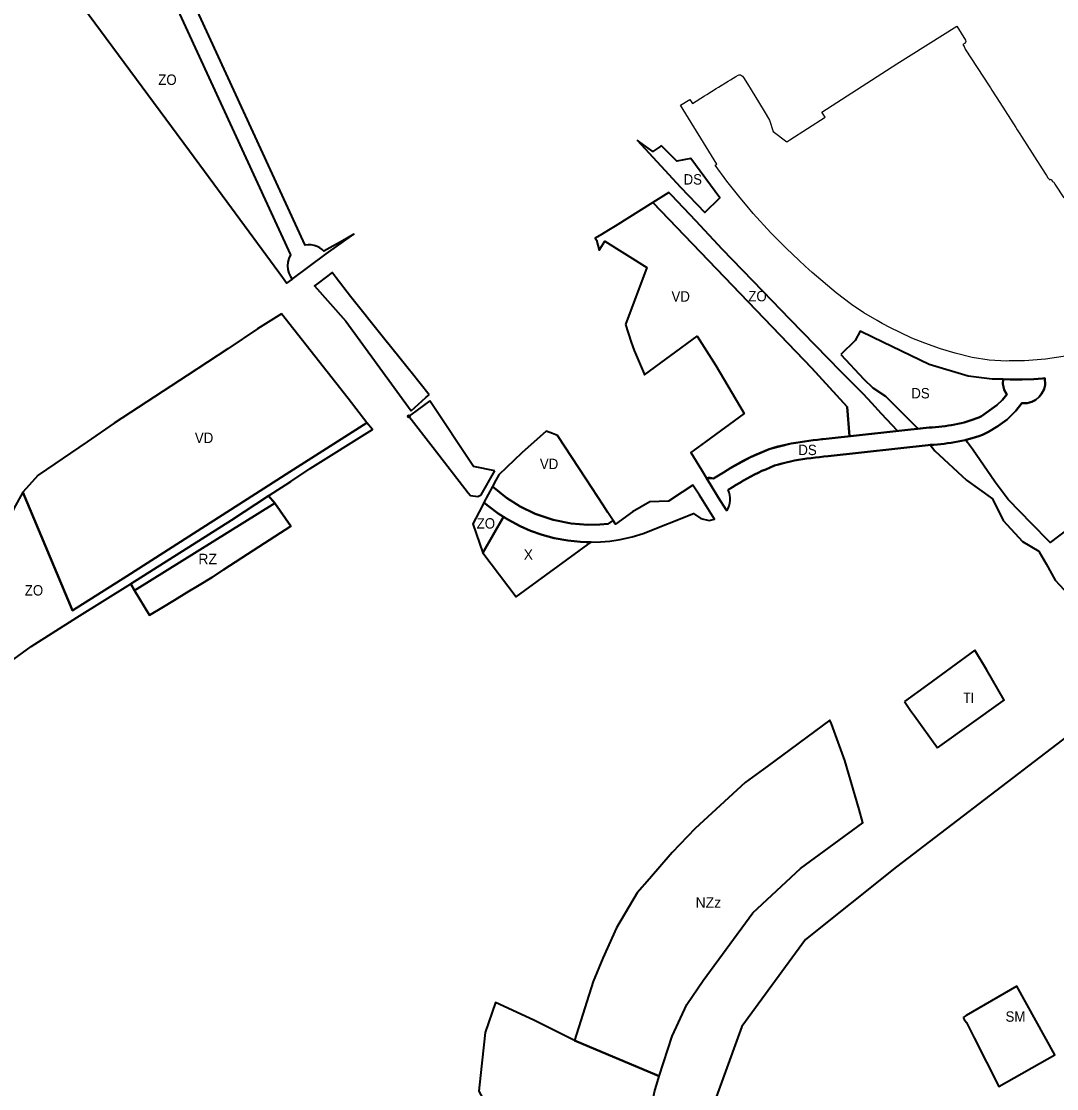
# Model space of a CAD drawing. Extents: x -650276 to -642489, y -1074311 to -1066720.
# Drawn here: x -647921 to -646730, y -1072933 to -1071705 of the extents above; entities that cross this region are included whole.
import ezdxf

# ---------------------------------------------------------------- set-up
doc = ezdxf.new("R2010")
doc.units = 0
doc.header["$LTSCALE"] = 4.8
doc.header["$PDMODE"] = 32
doc.header["$PDSIZE"] = 2.4
for name, color, linetype, lineweight in [('15', 7, 'Continuous', 35), ('18', 7, 'Continuous', 35), ('24', 7, 'Continuous', 35), ('30', 7, 'Continuous', 35), ('35', 7, 'Continuous', 35), ('42', 7, 'Continuous', 35), ('46', 7, 'Continuous', 35), ('48', 7, 'Continuous', 35), ('51', 7, 'Continuous', 35), ('54', 7, 'Continuous', 35), ('61', 7, 'Continuous', 25), ('8', 7, 'Continuous', 35)]:
    doc.layers.add(name, color=color, linetype=linetype, lineweight=lineweight)
doc.layers.add('62', color=7, linetype='Continuous')

msp = doc.modelspace()

# ---------------------------------------------------------------- linework, layer by layer
at = {"layer": '15'}
msp.add_lwpolyline([(-647795.4, -1072352.415), (-647679.66, -1072279.15), (-647637.082, -1072251.377), (-647629.67, -1072259.82), (-647791.198, -1072360.119)], close=True, dxfattribs=at)
for points in [[(-647629.67, -1072259.82), (-647637.082, -1072251.377), (-647679.66, -1072279.15)], [(-647679.66, -1072279.15), (-647795.4, -1072352.415), (-647791.198, -1072360.119), (-647629.67, -1072259.82)]]:
    msp.add_lwpolyline(points, dxfattribs=at)
at = {"layer": '18'}
msp.add_lwpolyline([(-646837.81, -1072851.3), (-646836.5, -1072853.76), (-646833.67, -1072857.15), (-646824.89, -1072874.66), (-646796.68, -1072930.92), (-646732.28, -1072894.29), (-646775.85, -1072815.39), (-646834.08, -1072849.15)], close=True, dxfattribs=at)
at = {"layer": '24'}
for p, q in [((-646978.602, -1072088.66), (-646951.95, -1072116.84)), ((-647113.646, -1072224.274), (-647124.81, -1072231.168))]:
    msp.add_line(p, q, dxfattribs=at)
for points in [[(-647782.97, -1071619.278), (-647769.498, -1071636.647), (-647758.994, -1071653.513), (-647743.48, -1071687.426), (-647611.514, -1071974.086)], [(-647570.747, -1071972.644), (-647538.922, -1071950.099), (-647551.962, -1071958.049), (-647573.283, -1071969.627), (-647575.415, -1071967.709), (-647577.881, -1071965.979), (-647581.036, -1071964.346), (-647584.363, -1071963.196), (-647588.064, -1071962.51), (-647591.518, -1071962.387), (-647594.731, -1071962.714), (-647725.614, -1071678.405), (-647726.774, -1071675.885), (-647725.629, -1071678.373)], [(-647184.81, -1071848.61), (-647185.62, -1071849.12), (-647194.96, -1071854.93), (-647205.62, -1071847.24), (-647212.66, -1071842.15)], [(-647212.66, -1071842.15), (-647163.08, -1071896.13), (-647135.015, -1071925.145), (-647135.015, -1071925.145)], [(-647135.015, -1071925.145), (-647135.015, -1071925.145), (-647117.709, -1071908.3), (-647151.07, -1071863.08), (-647167.15, -1071866.22), (-647184.81, -1071848.61)], [(-647611.514, -1071974.086), (-647613.455, -1071978.031), (-647614.654, -1071982.238), (-647615.083, -1071986.65), (-647614.76, -1071990.762), (-647613.637, -1071995.081), (-647611.779, -1071999.069), (-647609.808, -1072001.962), (-647570.747, -1071972.644)], [(-647542.57, -1072021.99), (-647558.97, -1072000.62), (-647563.77, -1071994.38), (-647579.885, -1072006.501)], [(-647579.885, -1072006.501), (-647584.202, -1072009.747), (-647547.916, -1072050.439), (-647473.022, -1072153.375)], [(-647452.23, -1072134.91), (-647472.86, -1072109.13), (-647474.72, -1072106.81), (-647485.6, -1072093.2), (-647504.73, -1072069.29), (-647542.57, -1072021.99)], [(-646790.432, -1072129.195), (-646791.977, -1072122.305), (-646791.84, -1072117.172), (-646804.27, -1072116.98), (-646832.01, -1072113.66), (-646876.83, -1072100.12), (-646941.054, -1072069.172), (-646956.04, -1072061.95), (-646962.041, -1072072.379), (-646978.602, -1072088.66)], [(-646951.95, -1072116.84), (-646941.45, -1072126.84), (-646927.14, -1072136.74), (-646891.05, -1072172.79), (-646890.044, -1072174.056), (-646876.712, -1072172.592), (-646873.495, -1072172.799), (-646862.09, -1072171.444), (-646840.102, -1072167.623), (-646825.169, -1072163.164), (-646816.74, -1072159.571), (-646799, -1072147), (-646792.58, -1072140.847), (-646787.481, -1072134.643), (-646790.432, -1072129.195)], [(-646816.74, -1072159.571), (-646799, -1072147), (-646792.58, -1072140.847), (-646787.481, -1072134.643), (-646790.343, -1072129.36), (-646791.977, -1072122.305), (-646791.84, -1072117.172), (-646783.449, -1072117.302), (-646769.668, -1072117.517), (-646756.298, -1072117), (-646746.547, -1072116.221), (-646743.596, -1072115.985), (-646743.411, -1072123.612), (-646744.554, -1072128.415), (-646747.39, -1072134.069), (-646750.164, -1072137.467), (-646753.929, -1072140.612), (-646758.736, -1072143.137), (-646763.959, -1072144.535), (-646770.057, -1072144.677), (-646777.129, -1072153.576), (-646787.223, -1072163.402), (-646797.713, -1072171.151), (-646808.466, -1072177.78)], [(-646808.466, -1072177.78), (-646797.713, -1072171.151), (-646787.223, -1072163.402), (-646777.129, -1072153.576), (-646770.057, -1072144.677), (-646763.959, -1072144.535), (-646758.736, -1072143.137), (-646753.929, -1072140.612), (-646750.164, -1072137.467), (-646747.39, -1072134.069), (-646744.554, -1072128.415), (-646743.411, -1072123.612), (-646743.596, -1072115.985), (-646746.547, -1072116.221), (-646756.298, -1072117), (-646769.668, -1072117.517), (-646783.449, -1072117.302), (-646791.84, -1072117.172), (-646791.977, -1072122.305), (-646790.343, -1072129.36), (-646787.481, -1072134.643), (-646792.58, -1072140.847), (-646799, -1072147), (-646816.74, -1072159.571)], [(-647451.21, -1072142.08), (-647473.12, -1072157.91), (-647475.57, -1072159.74), (-647475.57, -1072159.74)], [(-647473.022, -1072153.375), (-647455.83, -1072137.96), (-647452.23, -1072134.91)], [(-647376.68, -1072222.29), (-647401.221, -1072217.342), (-647451.21, -1072142.08)], [(-647475.57, -1072159.74), (-647447.73, -1072195.72), (-647407.34, -1072247.93)], [(-647124.81, -1072231.168), (-647113.646, -1072224.274), (-647109.342, -1072221.634), (-647104.989, -1072219.005), (-647100.583, -1072216.405), (-647096.114, -1072213.845), (-647091.574, -1072211.346), (-647086.955, -1072208.921), (-647082.249, -1072206.591), (-647077.456, -1072204.373), (-647072.72, -1072202.352), (-647060.973, -1072197.439), (-647055.906, -1072195.893), (-647050.82, -1072194.5), (-647045.722, -1072193.245), (-647040.618, -1072192.117), (-647035.515, -1072191.104), (-647030.417, -1072190.192), (-647025.33, -1072189.37), (-647020.254, -1072188.623), (-647015.192, -1072187.939), (-647010.148, -1072187.308), (-647005.124, -1072186.715), (-647000.12, -1072186.148), (-646995.137, -1072185.597), (-646876.712, -1072172.592), (-646873.495, -1072172.799), (-646869.667, -1072172.366), (-646865.866, -1072171.917), (-646862.09, -1072171.444), (-646858.343, -1072170.937), (-646854.627, -1072170.389), (-646850.941, -1072169.791), (-646847.291, -1072169.137), (-646843.678, -1072168.416), (-646840.102, -1072167.623), (-646836.573, -1072166.751), (-646833.091, -1072165.791), (-646829.66, -1072164.739), (-646826.287, -1072163.588), (-646822.975, -1072162.332), (-646819.733, -1072160.968), (-646816.74, -1072159.571)], [(-646816.74, -1072159.571), (-646819.733, -1072160.968), (-646822.975, -1072162.332), (-646826.287, -1072163.588), (-646829.66, -1072164.739), (-646833.091, -1072165.791), (-646836.573, -1072166.751), (-646840.102, -1072167.623), (-646843.678, -1072168.416), (-646847.291, -1072169.137), (-646850.941, -1072169.791), (-646854.627, -1072170.389), (-646858.343, -1072170.937), (-646862.09, -1072171.444), (-646865.866, -1072171.917), (-646869.667, -1072172.366), (-646873.495, -1072172.799), (-646876.712, -1072172.592), (-646995.137, -1072185.597), (-647000.12, -1072186.148), (-647005.124, -1072186.715), (-647010.148, -1072187.308), (-647015.192, -1072187.939), (-647020.254, -1072188.623), (-647025.33, -1072189.37), (-647030.417, -1072190.192), (-647035.515, -1072191.104), (-647040.618, -1072192.117), (-647045.722, -1072193.245), (-647050.82, -1072194.5), (-647055.906, -1072195.893), (-647060.973, -1072197.439), (-647072.72, -1072202.352), (-647077.456, -1072204.373), (-647082.249, -1072206.591), (-647086.955, -1072208.921), (-647091.574, -1072211.346), (-647096.114, -1072213.845), (-647100.583, -1072216.405), (-647104.989, -1072219.005), (-647109.342, -1072221.634), (-647113.646, -1072224.274)], [(-646808.466, -1072177.78), (-646811.621, -1072179.254), (-646815.549, -1072180.906), (-646819.509, -1072182.408), (-646823.496, -1072183.769), (-646827.501, -1072184.997), (-646831.517, -1072186.103), (-646835.538, -1072187.097), (-646839.556, -1072187.988), (-646843.569, -1072188.789), (-646847.575, -1072189.507), (-646851.567, -1072190.155), (-646855.545, -1072190.741), (-646859.506, -1072191.276), (-646863.448, -1072191.771), (-646867.371, -1072192.234), (-646871.271, -1072192.675), (-646874.517, -1072192.471), (-646992.937, -1072205.475), (-646997.894, -1072206.024), (-647002.826, -1072206.583), (-647007.734, -1072207.162), (-647012.612, -1072207.773), (-647017.46, -1072208.427), (-647022.278, -1072209.136), (-647027.061, -1072209.91), (-647031.807, -1072210.758), (-647036.512, -1072211.693), (-647041.174, -1072212.723), (-647045.786, -1072213.858), (-647050.344, -1072215.107), (-647054.841, -1072216.479), (-647064.868, -1072220.746), (-647069.33, -1072222.651), (-647073.611, -1072224.631), (-647077.867, -1072226.739), (-647082.102, -1072228.962), (-647086.322, -1072231.285), (-647090.531, -1072233.695), (-647094.737, -1072236.177), (-647098.944, -1072238.718), (-647103.164, -1072241.306), (-647108.131, -1072244.373)], [(-646874.517, -1072192.471), (-646871.271, -1072192.675), (-646867.371, -1072192.234), (-646863.448, -1072191.771), (-646859.506, -1072191.276), (-646855.545, -1072190.741), (-646851.567, -1072190.155), (-646847.575, -1072189.507), (-646843.569, -1072188.789), (-646839.556, -1072187.988), (-646835.538, -1072187.097), (-646831.517, -1072186.103), (-646827.501, -1072184.997), (-646823.496, -1072183.769), (-646819.509, -1072182.408), (-646815.549, -1072180.906), (-646811.621, -1072179.254), (-646808.466, -1072177.78)], [(-647108.131, -1072244.373), (-647103.164, -1072241.306), (-647098.944, -1072238.718), (-647094.737, -1072236.177), (-647090.531, -1072233.695), (-647086.322, -1072231.285), (-647082.102, -1072228.962), (-647077.867, -1072226.739), (-647073.611, -1072224.631), (-647069.33, -1072222.651), (-647064.868, -1072220.746), (-647054.841, -1072216.479), (-647050.344, -1072215.107), (-647045.786, -1072213.858), (-647041.174, -1072212.723), (-647036.512, -1072211.693), (-647031.807, -1072210.758), (-647027.061, -1072209.91), (-647022.278, -1072209.136), (-647017.46, -1072208.427), (-647012.612, -1072207.773), (-647007.734, -1072207.162), (-647002.826, -1072206.583), (-646997.894, -1072206.024), (-646992.937, -1072205.475), (-646874.517, -1072192.471)], [(-647407.34, -1072247.93), (-647404.45, -1072250.66), (-647396.25, -1072252.14), (-647392.34, -1072250.02), (-647376.68, -1072222.29)], [(-647109.812, -1072268.588), (-647110.55, -1072267.42), (-647119.07, -1072253.56), (-647128.07, -1072238.83), (-647133, -1072230.754)], [(-647133, -1072230.754), (-647128.07, -1072238.83), (-647119.07, -1072253.56), (-647110.55, -1072267.42), (-647109.812, -1072268.588)]]:
    msp.add_lwpolyline(points, dxfattribs=at)
msp.add_lwpolyline([(-647265.793, -1072304.439), (-647255.16, -1072304.123), (-647244.428, -1072303.192), (-647232.368, -1072301.4), (-647218.5, -1072298.335), (-647205.975, -1072294.599), (-647148.171, -1072271.47), (-647139.697, -1072277.484), (-647130.12, -1072279.44), (-647123.774, -1072277.899), (-647141.05, -1072250.54), (-647148.71, -1072238.76), (-647148.71, -1072238.76), (-647160.91, -1072246.82), (-647176.7, -1072257.24), (-647198.3, -1072258.09), (-647218.35, -1072269.67), (-647237.6, -1072283.78), (-647240.55, -1072279.42), (-647246.206, -1072283.328), (-647255.671, -1072284.192), (-647269.579, -1072284.489), (-647288.769, -1072283.003), (-647309.416, -1072278.875), (-647330.032, -1072271.935), (-647347.382, -1072263.623), (-647363.317, -1072253.632), (-647379.422, -1072240.675), (-647389.072, -1072258.845), (-647383.813, -1072263.219), (-647372.858, -1072271.363), (-647361.521, -1072278.584), (-647347.369, -1072286.111), (-647335.382, -1072291.341), (-647321.953, -1072296.073), (-647308.157, -1072299.786), (-647292.715, -1072302.646), (-647278.108, -1072304.147), (-647271.395, -1072304.452), (-647265.793, -1072304.439)], close=True, dxfattribs=at)
for centre, start, end in [((-646767.624, -1072120.384), 264.28146, 264.89913), ((-647130.12, -1072255.012), 77.44425, 96.77054), ((-647130.12, -1072255.012), 77.44425, 96.77054), ((-647130.12, -1072255.012), 326.23773, 25.81772), ((-647130.12, -1072255.012), 326.23773, 25.81772)]:
    msp.add_arc(centre, 24.428, start, end, dxfattribs=at)
msp.add_point((-647475.57, -1072159.74), dxfattribs=at)
at = {"layer": '30'}
for points in [[(-646824.42, -1072428.58), (-646878.91, -1072468.54), (-646905.18, -1072487.8)], [(-646867.283, -1072540.984), (-646791.569, -1072487.198), (-646790.354, -1072486.136), (-646810.77, -1072451.09), (-646824.42, -1072428.58)], [(-646905.18, -1072487.8), (-646898.1, -1072498.02), (-646893.64, -1072504.45), (-646867.283, -1072540.984)]]:
    msp.add_lwpolyline(points, dxfattribs=at)
at = {"layer": '35'}
for points in [[(-647226.41, -1072054.11), (-647219.64, -1072074.29), (-647216.23, -1072084.14), (-647204.78, -1072110.92), (-647204.38, -1072111.87), (-647143.76, -1072067.69), (-647122.33, -1072101.34), (-647089.54, -1072156.53), (-647134.17, -1072188.95), (-647151.05, -1072201.21), (-647138.65, -1072221.5), (-647133, -1072230.754), (-647124.81, -1072231.168), (-647104.989, -1072219.005), (-647082.249, -1072206.591), (-647060.973, -1072197.439), (-647035.515, -1072191.104), (-647010.148, -1072187.308), (-646995.137, -1072185.597), (-646968.503, -1072182.672), (-646971.283, -1072148.82), (-647011.762, -1072104.502), (-647194.903, -1071913.941), (-647238.1, -1071941), (-647245.71, -1071945.77), (-647253.67, -1071950.76), (-647261.12, -1071954.82), (-647259.7, -1071957.06), (-647256.53, -1071968.64), (-647253.85, -1071964.38), (-647249.92, -1071958.12), (-647201.53, -1071988.71)], [(-647246.563, -1072270.214), (-647251.85, -1072262.12), (-647271.38, -1072232.23), (-647304.32, -1072181.81), (-647310.33, -1072179.58), (-647317.33, -1072176.99), (-647345.42, -1072201.58), (-647372.1, -1072226.89), (-647375.551, -1072233.387), (-647379.422, -1072240.675), (-647363.317, -1072253.632), (-647347.382, -1072263.623), (-647330.032, -1072271.935), (-647309.416, -1072278.875), (-647288.769, -1072283.003), (-647269.579, -1072284.489), (-647255.671, -1072284.192), (-647246.206, -1072283.328), (-647240.55, -1072279.42)]]:
    msp.add_lwpolyline(points, close=True, dxfattribs=at)
for points in [[(-647621.97, -1072041.73), (-647649.76, -1072059.06), (-647683.63, -1072081.94), (-647730.53, -1072112.84), (-647814.58, -1072167.67), (-647845.58, -1072188.94), (-647901.91, -1072227.6), (-647919.68, -1072247.09), (-647862.615, -1072383.084)], [(-647523.71, -1072167.071), (-647545.44, -1072139.35), (-647621.97, -1072041.73)], [(-647862.615, -1072383.084), (-647800.2, -1072343.615), (-647642.504, -1072242.974), (-647616.719, -1072226.154), (-647523.71, -1072167.071)]]:
    msp.add_lwpolyline(points, dxfattribs=at)
at = {"layer": '42'}
for points in [[(-647743.48, -1071687.426), (-647611.514, -1071974.086), (-647613.455, -1071978.031), (-647614.654, -1071982.238), (-647615.083, -1071986.65), (-647614.76, -1071990.762), (-647613.637, -1071995.081), (-647611.779, -1071999.069), (-647609.808, -1072001.962), (-647616.12, -1072006.7), (-647621.06, -1072000), (-647644.38, -1071968.3), (-647705.291, -1071885.501), (-647727.85, -1071854.86), (-647857.52, -1071678.92)], [(-647637.082, -1072251.377), (-647611.306, -1072234.563), (-647589.02, -1072219.66), (-647517.51, -1072174.98), (-647523.71, -1072167.071), (-647616.719, -1072226.154), (-647642.504, -1072242.974), (-647800.2, -1072343.615)], [(-646643.55, -1072233.5), (-646737.449, -1072305.019), (-646738.951, -1072303.49), (-646758.684, -1072283.41), (-646785.958, -1072255.505), (-646800.76, -1072235.668), (-646826.893, -1072197.582), (-646832.718, -1072189.697), (-646834.279, -1072186.818), (-646833.373, -1072186.562), (-646835.538, -1072187.097), (-646839.556, -1072187.988), (-646843.569, -1072188.789), (-646847.575, -1072189.507), (-646851.567, -1072190.155), (-646855.545, -1072190.741), (-646859.506, -1072191.276), (-646863.448, -1072191.771), (-646867.371, -1072192.234), (-646871.271, -1072192.675), (-646874.517, -1072192.471), (-646875.509, -1072192.58), (-646870.21, -1072199.51), (-646833.75, -1072233.32), (-646803.98, -1072254.74), (-646791.59, -1072279.78), (-646769.24, -1072303.65), (-646750.58, -1072315.02), (-646750.12, -1072315.82), (-646742.32, -1072329.62), (-646731.82, -1072348.2), (-646696.83, -1072385.81)], [(-647800.2, -1072343.615), (-647862.615, -1072383.084), (-647919.68, -1072247.09), (-647930.36, -1072266.38), (-647934.86, -1072280.99), (-647939.26, -1072306.1), (-647942.54, -1072333.82), (-647950.2, -1072398.61), (-647956.786, -1072446.511), (-647958.82, -1072459.74), (-647910.27, -1072424.51), (-647857.52, -1072391.14), (-647795.4, -1072352.415)], [(-647795.4, -1072352.415), (-647679.66, -1072279.15), (-647637.082, -1072251.377)]]:
    msp.add_lwpolyline(points, dxfattribs=at)
for points in [[(-647011.762, -1072104.502), (-646971.283, -1072148.82), (-646968.503, -1072182.672), (-646942.928, -1072179.864), (-646913.373, -1072176.618), (-646931.653, -1072156.802), (-646942.78, -1072144.74), (-646952.48, -1072134.22), (-646964.8, -1072121.83), (-646977.59, -1072108.96), (-646978.45, -1072108.09), (-647036.8, -1072048.41), (-647068.31, -1072015.68), (-647114.59, -1071967.77), (-647145.38, -1071935), (-647173.14, -1071905.45), (-647174.57, -1071904.06), (-647176.32, -1071902.3), (-647194.903, -1071913.941)], [(-647390.58, -1072316.75), (-647366.505, -1072275.41), (-647372.858, -1072271.363), (-647383.813, -1072263.219), (-647389.072, -1072258.845), (-647391.3, -1072263.04), (-647401.88, -1072283.4)]]:
    msp.add_lwpolyline(points, close=True, dxfattribs=at)
at = {"layer": '46'}
msp.add_lwpolyline([(-647284.75, -1072877.79), (-647282.31, -1072878.82), (-647192.718, -1072916.582), (-647187.445, -1072918.804), (-647172.48, -1072872.92), (-647155.72, -1072836.46), (-647136.69, -1072808.98), (-647079.74, -1072731.1), (-647025.04, -1072679.96), (-646953.2, -1072627.45), (-646957.5, -1072612.09), (-646973.68, -1072555.68), (-646989.01, -1072513.62), (-646991.24, -1072509.24), (-647063.38, -1072562.42), (-647088.397, -1072580.865), (-647088.4, -1072580.868), (-647146.21, -1072634.02), (-647172.36, -1072661.69), (-647198.77, -1072691.71), (-647212.92, -1072708.05), (-647236.54, -1072748.09), (-647252.29, -1072783.24), (-647263.58, -1072809.97)], close=True, dxfattribs=at)
at = {"layer": '48'}
msp.add_lwpolyline([(-647293.317, -1072873.549), (-647293.351, -1072873.533), (-647331.82, -1072854.49), (-647375.92, -1072833.99), (-647387.64, -1072868.69), (-647392.96, -1072918.277), (-647394.87, -1072936.08), (-647388.62, -1072948.03), (-647395.47, -1072993.25), (-647367.45, -1073002.47), (-647353.78, -1073003.1), (-647213.99, -1073041.449), (-647210.396, -1073023.593), (-647207.176, -1073007.598), (-647192.93, -1072936.82), (-647187.445, -1072918.804), (-647192.718, -1072916.582), (-647282.31, -1072878.82), (-647284.75, -1072877.79)], close=True, dxfattribs=at)
at = {"layer": '51'}
msp.add_lwpolyline([(-647390.58, -1072316.75), (-647351.86, -1072367.52), (-647269.52, -1072307.17), (-647265.793, -1072304.439), (-647271.395, -1072304.452), (-647278.108, -1072304.147), (-647292.715, -1072302.646), (-647308.157, -1072299.786), (-647321.953, -1072296.073), (-647335.382, -1072291.341), (-647347.369, -1072286.111), (-647361.521, -1072278.584), (-647366.505, -1072275.41)], close=True, dxfattribs=at)
at = {"layer": '54'}
msp.add_lwpolyline([(-646516, -1072345), (-646685.823, -1072502.987), (-646914.429, -1072678.004), (-647018.969, -1072761.795), (-647092.194, -1072861.614), (-647161.068, -1073050.946)], dxfattribs=at)
at = {"layer": '61'}
msp.add_lwpolyline([(-646717.55, -1072090), (-646742.95, -1072093.96), (-646767.01, -1072095.86), (-646771.52, -1072095.92), (-646781.75, -1072096.04), (-646784.76, -1072096.01), (-646787.8, -1072096.24), (-646807.9, -1072095.03), (-646827.46, -1072092.09), (-646846.81, -1072087.28), (-646863.68, -1072082.09), (-646881.98, -1072075.61), (-646896.84, -1072069.83), (-646922.95, -1072057.25), (-646929.53, -1072053.65), (-646931, -1072052.81), (-646936.81, -1072049.5), (-646952.07, -1072040.55), (-646966.13, -1072031.23), (-646983.88, -1072017.52), (-647011.61, -1071994.42), (-647015.13, -1071991.01), (-647019.3, -1071987.12), (-647026.77, -1071980.29), (-647041.08, -1071966.71), (-647059.01, -1071948.52), (-647079.15, -1071926.49), (-647088.04, -1071915.77), (-647094.25, -1071908.29), (-647109.58, -1071889.27), (-647123, -1071870.89), (-647121.15, -1071869.68), (-647162.98, -1071801.68), (-647152.08, -1071795.15), (-647149.32, -1071799.92), (-647135.34, -1071791.17), (-647132.63, -1071789.47), (-647121.76, -1071782.65), (-647119.06, -1071780.95), (-647108.21, -1071774.17), (-647105.49, -1071772.47), (-647099.39, -1071768.65), (-647096.58, -1071767.23), (-647095.35, -1071766.89), (-647093.94, -1071766.95), (-647092.65, -1071767.48), (-647091.55, -1071768.46), (-647090.45, -1071769.99), (-647085.97, -1071777.09), (-647081.6, -1071784.03), (-647071.99, -1071799.81), (-647066.76, -1071808.54), (-647060.7, -1071819.12), (-647056.31, -1071832.13), (-647040.52, -1071843.958), (-647037.23, -1071841.82), (-646996.65, -1071815.45), (-647000.4, -1071809.69), (-646913.82, -1071754.1), (-646845.08, -1071711.06), (-646834.86, -1071727.2), (-646834.66, -1071728.69), (-646835.33, -1071730.32), (-646837.92, -1071732.14), (-646836.62, -1071734.14), (-646835.35, -1071737.24), (-646807.7, -1071779.69), (-646806.22, -1071781.97), (-646804.6, -1071784.61), (-646795.36, -1071798.85), (-646777.21, -1071827.55), (-646775.63, -1071830.04), (-646772.5, -1071834.88), (-646770.65, -1071837.91), (-646743.34, -1071880.3), (-646741.81, -1071882.7), (-646740.07, -1071885.5), (-646737.81, -1071887.58), (-646736.61, -1071887.04), (-646734.75, -1071889.65), (-646733.38, -1071890.49), (-646732.05, -1071892.58), (-646721.96, -1071908.47)], dxfattribs=at)
at = {"layer": '8'}
msp.add_lwpolyline([(-647629.67, -1072259.82), (-647611.51, -1072286.26), (-647648.09, -1072309.95), (-647688.26, -1072336.06), (-647702.35, -1072345.14), (-647716.62, -1072353.95), (-647730.97, -1072362.6), (-647745.32, -1072371.26), (-647759.68, -1072379.91), (-647774.04, -1072388.57), (-647791.198, -1072360.119)], close=True, dxfattribs=at)
for points in [[(-647629.67, -1072259.82), (-647791.198, -1072360.119), (-647774.04, -1072388.57)], [(-647774.04, -1072388.57), (-647759.68, -1072379.91), (-647745.32, -1072371.26), (-647730.97, -1072362.6), (-647716.62, -1072353.95), (-647702.35, -1072345.14), (-647688.26, -1072336.06), (-647648.09, -1072309.95), (-647611.51, -1072286.26), (-647629.67, -1072259.82)]]:
    msp.add_lwpolyline(points, dxfattribs=at)

# ---------------------------------------------------------------- texts
at = {"layer": '62'}
for s, width, p in [('ZO', 0.95, (-647763.886, -1071778.486)), ('DS', 0.95, (-647159.386, -1071893.148)), ('VD', 0.95, (-647173.311, -1072027.838)), ('ZO', 0.95, (-647084.886, -1072027.486)), ('DS', 0.95, (-646897.386, -1072139.148)), ('VD', 0.95, (-647721.74, -1072190.495)), ('DS', 0.95, (-647027.378, -1072204.379)), ('VD', 0.95, (-647324.74, -1072220.495)), ('ZO', 0.95, (-647397.457, -1072288.915)), ('ZO', 0.95, (-647917.457, -1072365.915)), ('TI', 0.85, (-646837.377, -1072489.619)), ('SM', 0.95, (-646788.938, -1072856.245))]:
    msp.add_text(s, height=12, dxfattribs=dict(at, width=width)).set_placement(p)
for s, p in [('X', (-647343.371, -1072324.801)), ('RZ', (-647717.713, -1072329.92)), ('NZz', (-647145.58, -1072725.109))]:
    msp.add_text(s, height=12, dxfattribs=at).set_placement(p)

doc.saveas('drawing.dxf')
